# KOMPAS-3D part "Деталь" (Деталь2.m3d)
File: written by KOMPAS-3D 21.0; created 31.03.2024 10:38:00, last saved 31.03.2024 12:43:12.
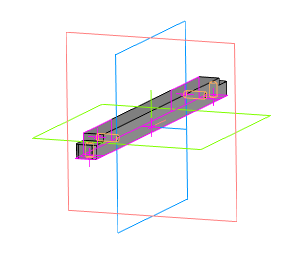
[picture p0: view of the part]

Document properties: Автор: Школа; Полное имя файла: C:\Users\Школа\Desktop\КУБСАТ ПРЕДПРОФФ\Ребро.m3d

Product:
- Part/product: Деталь
    Масса: 0.025406
  - Body: Тело 2
      Масса: 0.025615
  - Body: Тело 1
      Масса: 0.025615

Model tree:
1. Эскиз:1
2. Элемент выдавливания:1
     Расстояние 1 = 4
3. Элемент выдавливания:2
     Расстояние 1 = 4
4. Элемент выдавливания:3
     Расстояние 1 = 6
5. Отверстие:1  (with: Элемент выдавливания:1, Элемент выдавливания:3)  (labels: M2)
     Глубина выреза = 4; Диаметр отверстия = 1.56699; Угол конуса дна = 118; Расстояние 1 = -3; Расстояние 2 = 3
6. M2  (with: Элемент выдавливания:1)  (labels: cil0_24705-2004 coarse)
     Длина резьбы = 4; Шаг резьбы = 0.4; Номинальный диаметр резьбы = 2
7. Отверстие:2  (with: Элемент выдавливания:2, Элемент выдавливания:3, M2, Элемент выдавливания:1)  (labels: M2; cil0_24705-2004 coarse)
     Глубина выреза = 4; Диаметр отверстия = 1.56699; Угол конуса дна = 118; Расстояние 1 = -3; Расстояние 2 = 3; Длина резьбы = 4; Шаг резьбы = 0.4; Номинальный диаметр резьбы = 2
8. Эскиз:2  (with: Элемент выдавливания:1, Элемент выдавливания:3)
9. Отверстие:3  (with: Элемент выдавливания:1, Элемент выдавливания:2, M2)  (labels: M2; cil0_24705-2004 coarse)
     Глубина выреза = 6; Диаметр отверстия = 1.56699; Угол конуса дна = 118; Расстояние 1 = 3; Расстояние 2 = 79; Длина резьбы = 6; Шаг резьбы = 0.4; Номинальный диаметр резьбы = 2
10. Отверстие:4  (with: Элемент выдавливания:1, Элемент выдавливания:2, M2)  (labels: M2; cil0_24705-2004 coarse)
     Глубина выреза = 6; Диаметр отверстия = 1.56699; Угол конуса дна = 118; Расстояние 1 = 3; Расстояние 2 = 16; Длина резьбы = 6; Шаг резьбы = 0.4; Номинальный диаметр резьбы = 2
11. Скругление:1  (with: Элемент выдавливания:2, Элемент выдавливания:1)
     Радиус = 1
